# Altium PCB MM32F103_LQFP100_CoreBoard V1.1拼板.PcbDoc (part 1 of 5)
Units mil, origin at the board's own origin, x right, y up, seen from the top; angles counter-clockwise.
Board outline 7436.93 x 4329.96 mil, 2 copper layers (Top Layer, Bottom Layer); 260 components, 116 nets, 1796 pads, 452 vias.
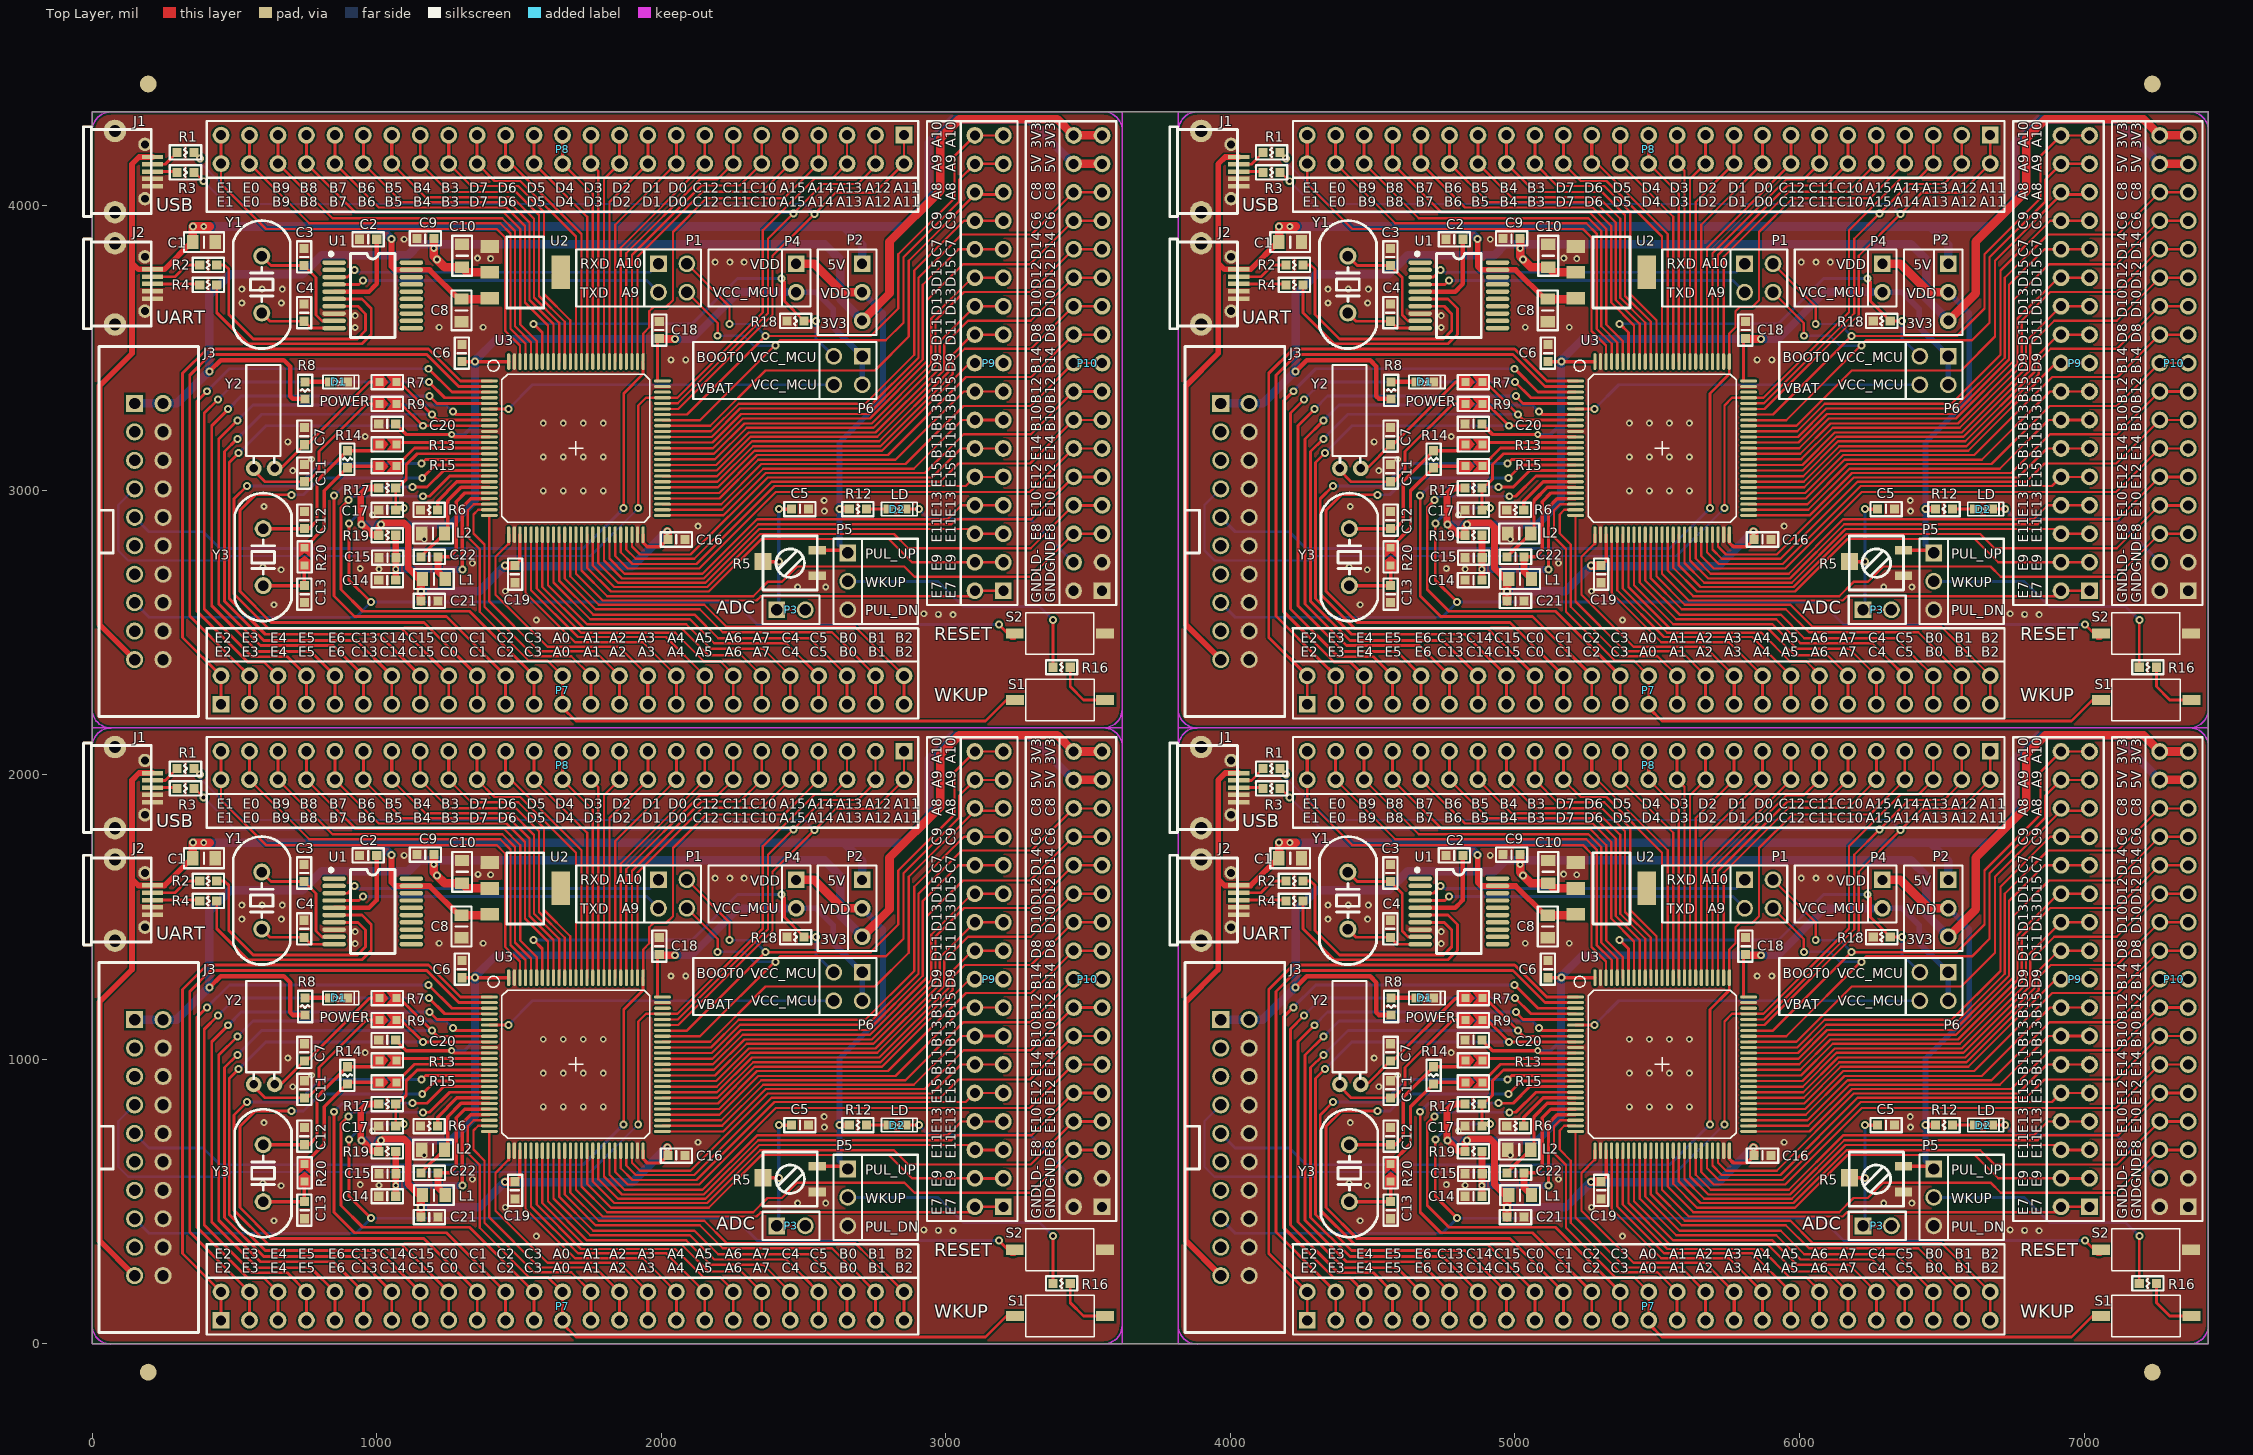
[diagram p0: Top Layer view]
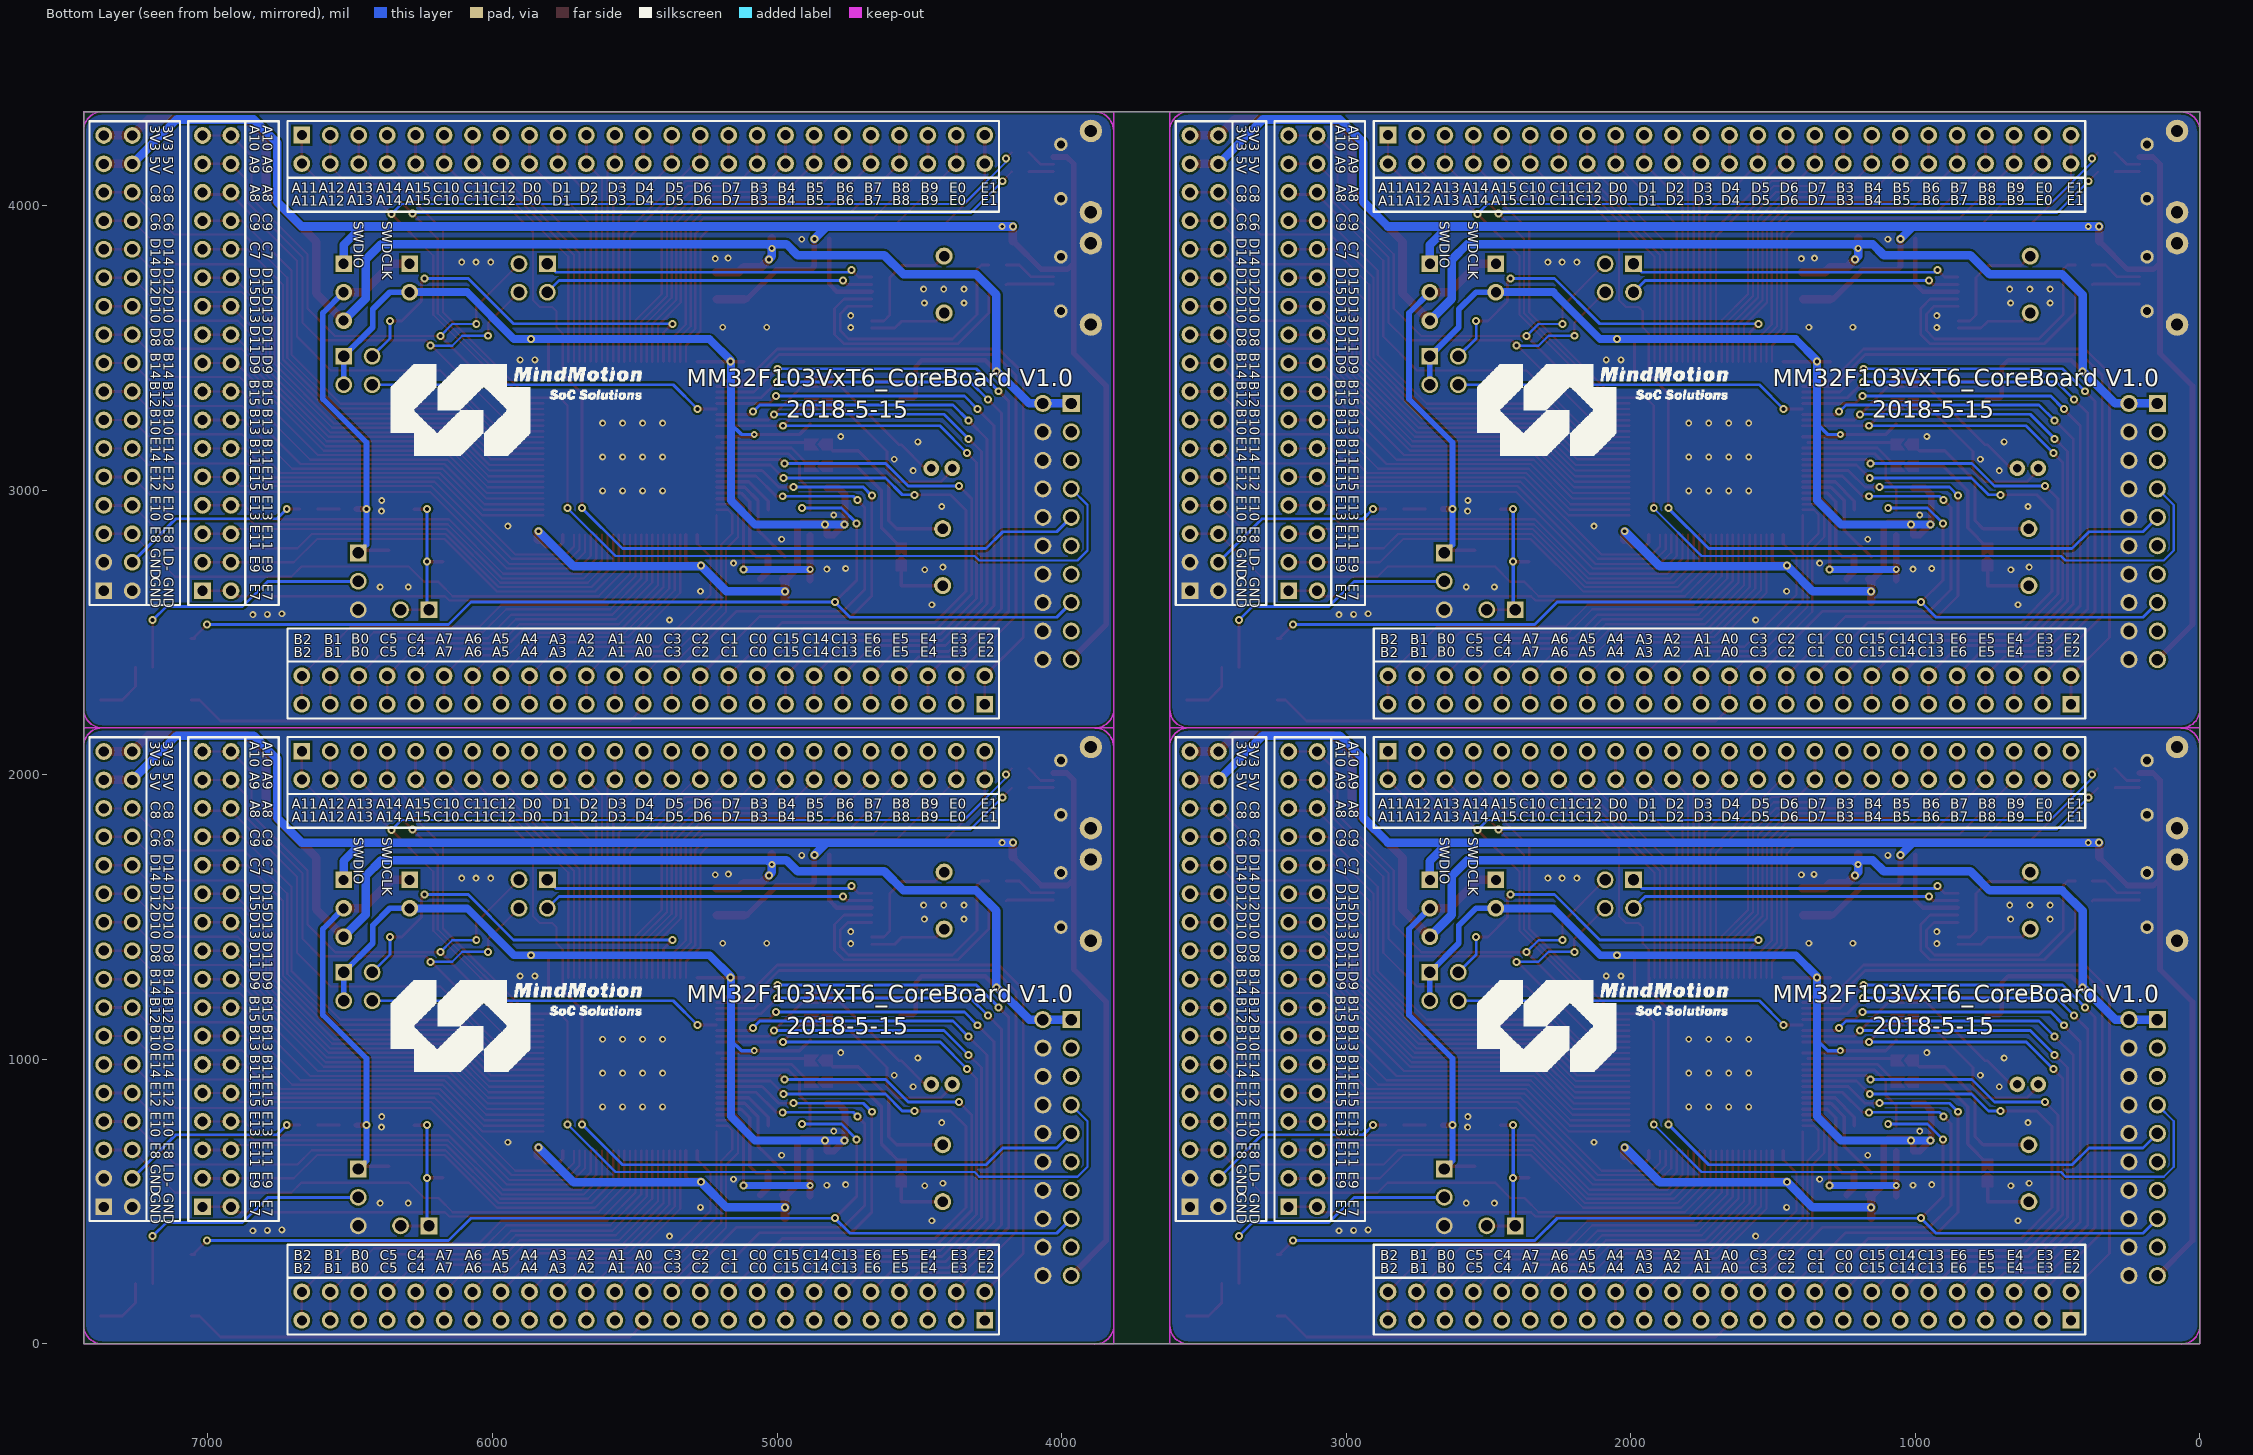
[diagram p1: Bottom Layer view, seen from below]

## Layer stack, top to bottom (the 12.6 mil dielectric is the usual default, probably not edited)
Top Layer: signal copper 1.4
Dielectric: dielectric 12.6, FR-4, Dk 4.8
Bottom Layer: signal copper 1.4

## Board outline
0,0 0,4329.96 7436.93,4329.96 7436.93,0

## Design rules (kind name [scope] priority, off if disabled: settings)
Clearance [All] p1: gap=7
MinimumSolderMaskSliver [All] p1: minsoldermaskwidth=7
PolygonConnect [All] p1: connectstyle=Direct reliefconductorwidth=10 reliefentries=4 polygonreliefangle="90 Angle"
RoutingVias [All] p1: holewidth=28 width=50 viastyle="Through Hole" minholewidth=14 minwidth=28 maxholewidth=30 maxwidth=50
SilkToSilkClearance [All] p1: silktosilkclearance=0
SilkscreenOverComponentPads [All] p1: minsilkscreentomaskgap=0
SolderMaskExpansion [All] p1: expansion=4
Width [All] p1: maxlimit=50 minlimit=8 preferedwidth=10
25 further rules are at their usual default settings.

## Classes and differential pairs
component class "MM32F103_LQFP100_CoreBoard V1.0": C1 C2 C3 C4 C5 C6 C7 C8 C9 C10 C11 C12 C13 C14 C15 C16 C17 C18 C19 C20 C21 C22 D1 D2 J1 J2 J3 L1 L2 P1 P2 P3 P4 P5 P6 P7 P8 P9 P10 P12 P14 R1 R2 R3 R4 R5 R6 R7 R8 R9 R12 R13 R14 R15 R16 R17 R18 R19 R20 S1 S2 U1 U2 U3 Y1 Y2 Y3

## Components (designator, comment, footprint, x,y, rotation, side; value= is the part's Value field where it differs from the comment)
C1 "4.7uF" C-0805 393,1707 r180 top
C1 "4.7uF" C-0805 4209.93,1707 r180 top
C1 "4.7uF" C-0805 393,3872 r180 top
C1 "4.7uF" C-0805 4209.93,3872 r180 top
C2 "104" C-0603 970,1717 r0 top
C2 "104" C-0603 4786.93,1717 r0 top
C2 "104" C-0603 970,3882 r0 top
C2 "104" C-0603 4786.93,3882 r0 top
C3 "22pF" C-0603 745,1655 r270 top
C3 "22pF" C-0603 4561.93,1655 r270 top
C3 "22pF" C-0603 745,3820 r270 top
C3 "22pF" C-0603 4561.93,3820 r270 top
C4 "22pF" C-0603 745,1459 r270 top
C4 "22pF" C-0603 4561.93,1459 r270 top
C4 "22pF" C-0603 745,3624 r270 top
C4 "22pF" C-0603 4561.93,3624 r270 top
C5 "104" C-0603 2487.23,769 r180 top
C5 "104" C-0603 6304.16,769 r180 top
C5 "104" C-0603 2487.23,2934 r180 top
C5 "104" C-0603 6304.16,2934 r180 top
C6 "104" C-0603 1299,1317 r90 top
C6 "104" C-0603 5115.93,1317 r90 top
C6 "104" C-0603 1299,3482 r90 top
C6 "104" C-0603 5115.93,3482 r90 top
C7 "15pF" C-0603 746,1025 r270 top
C7 "15pF" C-0603 4562.93,1025 r270 top
C7 "15pF" C-0603 746,3190 r270 top
C7 "15pF" C-0603 4562.93,3190 r270 top
C8 "4.7uF" C-0805 1298,1467 r90 top
C8 "4.7uF" C-0805 5114.93,1467 r90 top
C8 "4.7uF" C-0805 1298,3632 r90 top
C8 "4.7uF" C-0805 5114.93,3632 r90 top
C9 "104" C-0603 1171,1720 r0 top
C9 "104" C-0603 4987.93,1720 r0 top
C9 "104" C-0603 1171,3885 r0 top
C9 "104" C-0603 4987.93,3885 r0 top
C10 "10uF" C-0805 1300,1659 r270 top
C10 "10uF" C-0805 5116.93,1659 r270 top
C10 "10uF" C-0805 1300,3824 r270 top
C10 "10uF" C-0805 5116.93,3824 r270 top
C11 "15pF" C-0603 746,895 r270 top
C11 "15pF" C-0603 4562.93,895 r270 top
C11 "15pF" C-0603 746,3060 r270 top
C11 "15pF" C-0603 4562.93,3060 r270 top
C12 "22pF" C-0603 746,730 r270 top
C12 "22pF" C-0603 4562.93,730 r270 top
C12 "22pF" C-0603 746,2895 r270 top
C12 "22pF" C-0603 4562.93,2895 r270 top
C13 "22pF" C-0603 746,470 r90 top
C13 "22pF" C-0603 4562.93,470 r90 top
C13 "22pF" C-0603 746,2635 r90 top
C13 "22pF" C-0603 4562.93,2635 r90 top
C14 "1uF" C-0603 1037,519 r180 top
C14 "1uF" C-0603 4853.93,519 r180 top
C14 "1uF" C-0603 1037,2684 r180 top
C14 "1uF" C-0603 4853.93,2684 r180 top
C15 "103" C-0603 1038,598 r180 top
C15 "103" C-0603 4854.93,598 r180 top
C15 "103" C-0603 1038,2763 r180 top
C15 "103" C-0603 4854.93,2763 r180 top
C16 "104" C-0603 2053,662 r180 top
C16 "104" C-0603 5869.93,662 r180 top
C16 "104" C-0603 2053,2827 r180 top
C16 "104" C-0603 5869.93,2827 r180 top
C17 "104" C-0603 1037,765.86 r180 top
C17 "104" C-0603 4853.93,765.86 r180 top
C17 "104" C-0603 1037,2930.86 r180 top
C17 "104" C-0603 4853.93,2930.86 r180 top
C18 "104" C-0603 1993,1398 r90 top
C18 "104" C-0603 5809.93,1398 r90 top
C18 "104" C-0603 1993,3563 r90 top
C18 "104" C-0603 5809.93,3563 r90 top
C19 "104" C-0603 1486,540 r270 top
C19 "104" C-0603 5302.93,540 r270 top
C19 "104" C-0603 1486,2705 r270 top
C19 "104" C-0603 5302.93,2705 r270 top
C20 "104" C-0603 1037,1068 r180 top
C20 "104" C-0603 4853.93,1068 r180 top
C20 "104" C-0603 1037,3233 r180 top
C20 "104" C-0603 4853.93,3233 r180 top
C21 "1uF" C-0603 1185,446 r0 top
C21 "1uF" C-0603 5001.93,446 r0 top
C21 "1uF" C-0603 1185,2611 r0 top
C21 "1uF" C-0603 5001.93,2611 r0 top
C22 "1uF" C-0603 1185,601 r180 top
C22 "1uF" C-0603 5001.93,601 r180 top
C22 "1uF" C-0603 1185,2766 r180 top
C22 "1uF" C-0603 5001.93,2766 r180 top
D1 "RED" LED-0603 866,1216 r270 top
D1 "RED" LED-0603 4682.93,1216 r270 top
D1 "RED" LED-0603 866,3381 r270 top
D1 "RED" LED-0603 4682.93,3381 r270 top
D2 "BLUE" LED-0603 2829,769 r270 top
D2 "BLUE" LED-0603 6645.93,769 r270 top
D2 "BLUE" LED-0603 2829,2934 r270 top
D2 "BLUE" LED-0603 6645.93,2934 r270 top
J1 "USB_Micro_OX" USB_MICRO_OX_S 206,1955 r90 top
J1 "USB_Micro_OX" USB_MICRO_OX_S 4022.93,1955 r90 top
J1 "USB_Micro_OX" USB_MICRO_OX_S 206,4120 r90 top
J1 "USB_Micro_OX" USB_MICRO_OX_S 4022.93,4120 r90 top
J2 "USB_Micro_OX" USB_MICRO_OX_S 206,1560 r90 top
J2 "USB_Micro_OX" USB_MICRO_OX_S 4022.93,1560 r90 top
J2 "USB_Micro_OX" USB_MICRO_OX_S 206,3725 r90 top
J2 "USB_Micro_OX" USB_MICRO_OX_S 4022.93,3725 r90 top
J3 "CON20A" HEADERBG10X2H 149,1140 r90 top
J3 "CON20A" HEADERBG10X2H 3965.93,1140 r90 top
J3 "CON20A" HEADERBG10X2H 149,3305 r90 top
J3 "CON20A" HEADERBG10X2H 3965.93,3305 r90 top
L1 "Res Semi" C-0805 1201,523 r0 top
L1 "Res Semi" C-0805 5017.93,523 r0 top
L1 "Res Semi" C-0805 1201,2688 r0 top
L1 "Res Semi" C-0805 5017.93,2688 r0 top
L2 "Res Semi" C-0805 1198,682.86 r0 top
L2 "Res Semi" C-0805 5014.93,682.86 r0 top
L2 "Res Semi" C-0805 1198,2847.86 r0 top
L2 "Res Semi" C-0805 5014.93,2847.86 r0 top
P1 "Header 2X2" HDR2X2 1990,1631 r270 top
P1 "Header 2X2" HDR2X2 5806.93,1631 r270 top
P1 "Header 2X2" HDR2X2 1990,3796 r270 top
P1 "Header 2X2" HDR2X2 5806.93,3796 r270 top
P2 "Header 3" HDR1X3#1 2706,1631 r270 top
P2 "Header 3" HDR1X3#1 6522.93,1631 r270 top
P2 "Header 3" HDR1X3#1 2706,3796 r270 top
P2 "Header 3" HDR1X3#1 6522.93,3796 r270 top
P3 "Header 2" HDR1X2#1 2406,415 r0 top
P3 "Header 2" HDR1X2#1 6222.93,415 r0 top
P3 "Header 2" HDR1X2#1 2406,2580 r0 top
P3 "Header 2" HDR1X2#1 6222.93,2580 r0 top
P4 "Header 2" HDR1X2#2 2474,1631 r270 top
P4 "Header 2" HDR1X2#2 6290.93,1631 r270 top
P4 "Header 2" HDR1X2#2 2474,3796 r270 top
P4 "Header 2" HDR1X2#2 6290.93,3796 r270 top
P5 "Header 3" HDR1X3#2 2655,615 r270 top
P5 "Header 3" HDR1X3#2 6471.93,615 r270 top
P5 "Header 3" HDR1X3#2 2655,2780 r270 top
P5 "Header 3" HDR1X3#2 6471.93,2780 r270 top
P6 "Header 2X2" HDR2X2 2706,1305.94 r180 top
P6 "Header 2X2" HDR2X2 6522.93,1305.94 r180 top
P6 "Header 2X2" HDR2X2 2706,3470.94 r180 top
P6 "Header 2X2" HDR2X2 6522.93,3470.94 r180 top
P7 "Header 25X2" HDR2X25 453,83 r0 top
P7 "Header 25X2" HDR2X25 4269.93,83 r0 top
P7 "Header 25X2" HDR2X25 453,2248 r0 top
P7 "Header 25X2" HDR2X25 4269.93,2248 r0 top
P8 "Header 25X2" HDR2X25 2853,2083 r180 top
P8 "Header 25X2" HDR2X25 6669.93,2083 r180 top
P8 "Header 25X2" HDR2X25 2853,4248 r180 top
P8 "Header 25X2" HDR2X25 6669.93,4248 r180 top
P9 "Header 17X2" HDR2X17 3202,482 r90 top
P9 "Header 17X2" HDR2X17 7018.93,482 r90 top
P9 "Header 17X2" HDR2X17 3202,2647 r90 top
P9 "Header 17X2" HDR2X17 7018.93,2647 r90 top
P10 "Header 17X2" HDR2X17 3549,482 r90 top
P10 "Header 17X2" HDR2X17 7365.93,482 r90 top
P10 "Header 17X2" HDR2X17 3549,2647 r90 top
P10 "Header 17X2" HDR2X17 7365.93,2647 r90 top
R1 "22R" R-0603 328,2022 r0 top
R1 "22R" R-0603 4144.93,2022 r0 top
R1 "22R" R-0603 328,4187 r0 top
R1 "22R" R-0603 4144.93,4187 r0 top
R2 "22R" R-0603 408,1627 r0 top
R2 "22R" R-0603 4224.93,1627 r0 top
R2 "22R" R-0603 408,3792 r0 top
R2 "22R" R-0603 4224.93,3792 r0 top
R3 "22R" R-0603 328,1952 r0 top
R3 "22R" R-0603 4144.93,1952 r0 top
R3 "22R" R-0603 328,4117 r0 top
R3 "22R" R-0603 4144.93,4117 r0 top
R4 "22R" R-0603 408,1557 r0 top
R4 "22R" R-0603 4224.93,1557 r0 top
R4 "22R" R-0603 408,3722 r0 top
R4 "22R" R-0603 4224.93,3722 r0 top
R5 "10K" R-VR-S 2453,579 r90 top
R5 "10K" R-VR-S 6269.93,579 r90 top
R5 "10K" R-VR-S 2453,2744 r90 top
R5 "10K" R-VR-S 6269.93,2744 r90 top
R6 "0R" R-0603 1184,765.71 r180 top
R6 "0R" R-0603 5000.93,765.71 r180 top
R6 "0R" R-0603 1184,2930.71 r180 top
R6 "0R" R-0603 5000.93,2930.71 r180 top
R7 "NC" NC-0603#1 1009,1216.14 r0 top
R7 "NC" NC-0603#1 4825.93,1216.14 r0 top
R7 "NC" NC-0603#1 1009,3381.14 r0 top
R7 "NC" NC-0603#1 4825.93,3381.14 r0 top
R8 "4.7K" R-0603 748,1186 r270 top
R8 "4.7K" R-0603 4564.93,1186 r270 top
R8 "4.7K" R-0603 748,3351 r270 top
R8 "4.7K" R-0603 4564.93,3351 r270 top
R9 "NC" NC-0603#1 1009,1139.29 r0 top
R9 "NC" NC-0603#1 4825.93,1139.29 r0 top
R9 "NC" NC-0603#1 1009,3304.29 r0 top
R9 "NC" NC-0603#1 4825.93,3304.29 r0 top
R12 "3K" R-0603 2690.7,769 r180 top
R12 "3K" R-0603 6507.63,769 r180 top
R12 "3K" R-0603 2690.7,2934 r180 top
R12 "3K" R-0603 6507.63,2934 r180 top
R13 "NC" NC-0603#1 1009,997.43 r0 top
R13 "NC" NC-0603#1 4825.93,997.43 r0 top
R13 "NC" NC-0603#1 1009,3162.43 r0 top
R13 "NC" NC-0603#1 4825.93,3162.43 r0 top
R14 "510K" R-0603 897,944 r270 top
R14 "510K" R-0603 4713.93,944 r270 top
R14 "510K" R-0603 897,3109 r270 top
R14 "510K" R-0603 4713.93,3109 r270 top
R15 "NC" NC-0603#1 1009,920.57 r0 top
R15 "NC" NC-0603#1 4825.93,920.57 r0 top
R15 "NC" NC-0603#1 1009,3085.57 r0 top
R15 "NC" NC-0603#1 4825.93,3085.57 r0 top
R16 "1K" R-0603 3407,213 r0 top
R16 "1K" R-0603 7223.93,213 r0 top
R16 "1K" R-0603 3407,2378 r0 top
R16 "1K" R-0603 7223.93,2378 r0 top
R17 "47K" R-0603 1037,842.71 r180 top
R17 "47K" R-0603 4853.93,842.71 r180 top
R17 "47K" R-0603 1037,3007.71 r180 top
R17 "47K" R-0603 4853.93,3007.71 r180 top
R18 "4.7K" R-0603 2472,1430 r0 top
R18 "4.7K" R-0603 6288.93,1430 r0 top
R18 "4.7K" R-0603 2472,3595 r0 top
R18 "4.7K" R-0603 6288.93,3595 r0 top
R19 "0R" R-0603 1037,677 r180 top
R19 "0R" R-0603 4853.93,677 r180 top
R19 "0R" R-0603 1037,2842 r180 top
R19 "0R" R-0603 4853.93,2842 r180 top
R20 "510R" NC-0603#2 746,575 r90 top
R20 "510R" NC-0603#2 4562.93,575 r90 top
R20 "510R" NC-0603#2 746,2740 r90 top
R20 "510R" NC-0603#2 4562.93,2740 r90 top
S1 "SW-PB" 3x6x2.5 3281,171 r0 top
S1 "SW-PB" 3x6x2.5 7097.93,171 r0 top
S1 "SW-PB" 3x6x2.5 3281,2336 r0 top
S1 "SW-PB" 3x6x2.5 7097.93,2336 r0 top
S2 "SW-PB" 3x6x2.5 3280,404 r0 top
S2 "SW-PB" 3x6x2.5 7096.93,404 r0 top
S2 "SW-PB" 3x6x2.5 3280,2569 r0 top
S2 "SW-PB" 3x6x2.5 7096.93,2569 r0 top
U1 "CH340T" SSOP-20_208MIL 986,1520 r270 top
U1 "CH340T" SSOP-20_208MIL 4802.93,1520 r270 top
U1 "CH340T" SSOP-20_208MIL 986,3685 r270 top
U1 "CH340T" SSOP-20_208MIL 4802.93,3685 r270 top
U2 "LD1117" SOT223 1522,1601 r270 top
U2 "LD1117" SOT223 5338.93,1601 r270 top
U2 "LD1117" SOT223 1522,3766 r270 top
U2 "LD1117" SOT223 5338.93,3766 r270 top
U3 "MM32F103VET6" LQFP100 1700,983 r0 top
U3 "MM32F103VET6" LQFP100 5516.93,983 r0 top
U3 "MM32F103VET6" LQFP100 1700,3148 r0 top
U3 "MM32F103VET6" LQFP100 5516.93,3148 r0 top
Y1 "12M" X'TAL 596,1458 r90 top
Y1 "12M" X'TAL 4412.93,1458 r90 top
Y1 "12M" X'TAL 596,3623 r90 top
Y1 "12M" X'TAL 4412.93,3623 r90 top
Y2 "32.768K" X'TAL-32768 641,912 r180 top
Y2 "32.768K" X'TAL-32768 4457.93,912 r180 top
Y2 "32.768K" X'TAL-32768 641,3077 r180 top
Y2 "32.768K" X'TAL-32768 4457.93,3077 r180 top
Y3 "8M" X'TAL 601,500 r90 top
Y3 "8M" X'TAL 4417.93,500 r90 top
Y3 "8M" X'TAL 601,2665 r90 top
Y3 "8M" X'TAL 4417.93,2665 r90 top

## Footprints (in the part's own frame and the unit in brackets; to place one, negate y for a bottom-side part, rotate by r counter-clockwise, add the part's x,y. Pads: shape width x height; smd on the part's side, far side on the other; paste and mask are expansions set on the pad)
3x6x2.5 [mm]
  rect 1.6x0.9 smd: 1(-0.965,-1.85) 2(7.087,-1.85)
  silkscreen extent 0,-3.71 6.1,0
C-0603 [mil]
  rect 32x32 smd: 1(-30,0) 2(30,0)
  silkscreen extent -55,-25 55,25
C-0805 [mil]
  rect 40x50 smd: 1(-40,0) 2(40,0)
  silkscreen extent -70,-35 70,35
HDR1X2#1 [mm] "Connector; Header; 2 Position"
  rect 1.5x1.5 hole 1.016: 1(0,0)
  round 1.5 hole 1.016: 2(2.54,0)
  silkscreen extent -1.27,-1.27 3.81,1.27
HDR1X2#2 [mm] "Connector; Header; 2 Position"
  rect 1.5x1.5 hole 0.9: 1(0,0)
  round 1.5 hole 0.9: 2(2.54,0)
  silkscreen extent -1.27,-1.27 3.81,1.27
HDR1X3#1 [mm] "Connector; Header; 3 Position"
  rect 1.5x1.5 hole 0.9: 1(0,0)
  round 1.5 hole 0.9: 2(2.54,0) 3(5.08,0)
  silkscreen extent -1.27,-1.27 6.35,1.27
HDR1X3#2 [mm] "Connector; Header; 3 Position"
  rect 1.5x1.5 hole 1.016: 1(0,0)
  round 1.5 hole 1.016: 2(2.54,0) 3(5.08,0)
  silkscreen extent -1.27,-1.27 6.35,1.27
HDR2X2 [mm] "Connector; Header; 2x2 Position"
  rect 1.5x1.5 hole 1.016: 1(0,0)
  round 1.5 hole 1.016: 2(0,2.54) 3(2.54,0) 4(2.54,2.54)
  silkscreen extent -1.27,-1.27 3.81,3.81
HDR2X17 [mm] "Connector; Header; 17x2 Position"
  rect 1.5x1.5 hole 0.9: 1(0,0)
  round 1.5 hole 0.9: 2(0,2.54) 3(2.54,0) 4(2.54,2.54) 5(5.08,0) 6(5.08,2.54) 7(7.62,0) 8(7.62,2.54) 9(10.16,0) 10(10.16,2.54) 11(12.7,0) 12(12.7,2.54) 13(15.24,0) 14(15.24,2.54) 15(17.78,0) 16(17.78,2.54) 17(20.32,0) 18(20.32,2.54) 19(22.86,0) 20(22.86,2.54) 21(25.4,0) 22(25.4,2.54) 23(27.94,0) 24(27.94,2.54) 25(30.48,0) 26(30.48,2.54) 27(33.02,0) 28(33.02,2.54) 29(35.56,0) 30(35.56,2.54) 31(38.1,0) 32(38.1,2.54) 33(40.64,0) 34(40.64,2.54)
  silkscreen extent -1.27,-1.27 41.91,3.81
HDR2X25 [mm] "Connector; Header; 25x2 Position"
  rect 1.5x1.5 hole 0.9: 1(0,0)
  round 1.5 hole 0.9: 2(0,2.54) 3(2.54,0) 4(2.54,2.54) 5(5.08,0) 6(5.08,2.54) 7(7.62,0) 8(7.62,2.54) 9(10.16,0) 10(10.16,2.54) 11(12.7,0) 12(12.7,2.54) 13(15.24,0) 14(15.24,2.54) 15(17.78,0) 16(17.78,2.54) 17(20.32,0) 18(20.32,2.54) 19(22.86,0) 20(22.86,2.54) 21(25.4,0) 22(25.4,2.54) 23(27.94,0) 24(27.94,2.54) 25(30.48,0) 26(30.48,2.54) 27(33.02,0) 28(33.02,2.54) 29(35.56,0) 30(35.56,2.54) 31(38.1,0) 32(38.1,2.54) 33(40.64,0) 34(40.64,2.54) 35(43.18,0) 36(43.18,2.54) 37(45.72,0) 38(45.72,2.54) 39(48.26,0) 40(48.26,2.54) 41(50.8,0) 42(50.8,2.54) 43(53.34,0) 44(53.34,2.54) 45(55.88,0) 46(55.88,2.54) 47(58.42,0) 48(58.42,2.54) 49(60.96,0) 50(60.96,2.54)
  silkscreen extent -1.27,-1.27 62.23,3.81
HEADERBG10X2H [mil]
  rect 60x60 hole 40: 1(0,0)
  round 60 hole 40: 2(0,-100) 3(-100,0) 4(-100,-100) 5(-200,0) 6(-200,-100) 7(-300,0) 8(-300,-100) 9(-400,0) 10(-400,-100) 11(-500,0) 12(-500,-100) 13(-600,0) 14(-600,-100) 15(-700,0) 16(-700,-100) 17(-800,0) 18(-800,-100) 19(-900,0) 20(-900,-100)
  silkscreen extent -1100,-225 200,125
LED-0603 [mm]
  rect 0.8x0.8 smd: 1(0,-0.8) 2(0,0.8)
  silkscreen extent -0.6,-1.4 0.6,1.8
LQFP100 [mm]
  oval 1.5x0.279 smd: 1(-7.725,6) 2(-7.725,5.5) 3(-7.725,5) 4(-7.725,4.5) 5(-7.725,4) 6(-7.725,3.5) 7(-7.725,3) 8(-7.725,2.5) 9(-7.725,2) 10(-7.725,1.5) 11(-7.725,1) 12(-7.725,0.5) 13(-7.725,0) 14(-7.725,-0.5) 15(-7.725,-1) 16(-7.725,-1.5) 17(-7.725,-2) 18(-7.725,-2.5) 19(-7.725,-3) 20(-7.725,-3.5) 21(-7.725,-4) 22(-7.725,-4.5) 23(-7.725,-5) 24(-7.725,-5.5) 25(-7.725,-6) 51(7.725,-6) 52(7.725,-5.5) 53(7.725,-5) 54(7.725,-4.5) 55(7.725,-4) 56(7.725,-3.5) 57(7.725,-3) 58(7.725,-2.5) 59(7.725,-2) 60(7.725,-1.5) 61(7.725,-1) 62(7.725,-0.5) 63(7.725,0) 64(7.725,0.5) 65(7.725,1) 66(7.725,1.5) 67(7.725,2) 68(7.725,2.5) 69(7.725,3) 70(7.725,3.5) 71(7.725,4) 72(7.725,4.5) 73(7.725,5) 74(7.725,5.5) 75(7.725,6)
  oval 0.279x1.5 smd: 26(-6,-7.725) 27(-5.5,-7.725) 28(-5,-7.725) 29(-4.5,-7.725) 30(-4,-7.725) 31(-3.5,-7.725) 32(-3,-7.725) 33(-2.5,-7.725) 34(-2,-7.725) 35(-1.5,-7.725) 36(-1,-7.725) 37(-0.5,-7.725) 38(0,-7.725) 39(0.5,-7.725) 40(1,-7.725) 41(1.5,-7.725) 42(2,-7.725) 43(2.5,-7.725) 44(3,-7.725) 45(3.5,-7.725) 46(4,-7.725) 47(4.5,-7.725) 48(5,-7.725) 49(5.5,-7.725) 50(6,-7.725) 76(6,7.725) 77(5.5,7.725) 78(5,7.725) 79(4.5,7.725) 80(4,7.725) 81(3.5,7.725) 82(3,7.725) 83(2.5,7.725) 84(2,7.725) 85(1.5,7.725) 86(1,7.725) 87(0.5,7.725) 88(0,7.725) 89(-0.5,7.725) 90(-1,7.725) 91(-1.5,7.725) 92(-2,7.725) 93(-2.5,7.725) 94(-3,7.725) 95(-3.5,7.725) 96(-4,7.725) 97(-4.5,7.725) 98(-5,7.725) 99(-5.5,7.725) 100(-6,7.725)
  silkscreen extent -7.86,-6.6 6.6,7.87
NC-0603#1 [mil]
  rect 28x28 smd: 1(0,-1) 2(60,-1)
  Top Layer region: -22,-21 16,-21 32,-1 16,19 -22,19
  Top Layer region: 26,19 42,-1 26,-21 78,-21 78,19
  silkscreen extent -27,-26 83,24
NC-0603#2 [mil]
  rect 28x28 smd: 1(-4,-0.33) 2(58,-0.33)
  Top Layer region: -24,-20.33 14,-20.33 30,-0.33 14,19.67 -24,19.67
  Top Layer region: 24,19.67 40,-0.33 24,-20.33 76,-20.33 76,19.67
  silkscreen extent -29,-25 81,25
R-0603 [mil]
  rect 32x32 smd: 1(-30,0) 2(30,0)
  silkscreen extent -55,-25 55,25
R-VR-S [mil]
  rect 30x60 smd: 1(-45,-95) 3(45,-95)
  rect 60x60 smd: 2(5,95)
  silkscreen extent -95,-95 95,95
SOT223 [mil]
  rect 45x65 smd: 1(-91,-125) 2(0,-125) 3(91,-125)
  rect 118x65 smd: 4(0,125)
  silkscreen extent -125,-65 125,65
SSOP-20_208MIL [mm]
  oval 0.4x2.1 smd mask+0.051: 1(-2.925,-3.45) 2(-2.275,-3.45) 3(-1.625,-3.45) 4(-0.975,-3.45) 5(-0.325,-3.45) 6(0.325,-3.45) 7(0.975,-3.45) 8(1.625,-3.45) 9(2.275,-3.45) 10(2.925,-3.45) 11(2.925,3.45) 12(2.275,3.45) 13(1.625,3.45) 14(0.975,3.45) 15(0.325,3.45) 16(-0.325,3.45) 17(-0.975,3.45) 18(-1.625,3.45) 19(-2.275,3.45) 20(-2.925,3.45)
  silkscreen extent -3.85,-3.86 3.75,2
USB_MICRO_OX_S [mm]
  rect 0.4x1.905 smd: 1(1.3,-0.153) 2(0.65,-0.153) 3(0,-0.153) 4(-0.65,-0.153) 5(-1.3,-0.153)
  round 1.2 hole 0.7: 6(2.425,0.52) 7(-2.425,0.52)
  round 2 hole 1.1: 8(-3.625,3.2) 9(3.625,3.2)
  silkscreen extent -4,-0.04 4,6
X'TAL [mil]
  round 60 hole 37: 1(0,0) 2(200,0)
  silkscreen extent -125,-100 325,100
X'TAL-32768 [mil]
  round 55 hole 30: 1(73.35,0) 2(0,0)
  silkscreen extent -21,-363 99,-20

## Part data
C1 C1 C1 C1 C2 C2 C2 C2 C3 C3 C3 C3 C4 C4 C4 C4 C5 C5 C5 C5 C6 C6 C6 C6 C7 C7 C7 C7 C8 C8 C8 C8 C9 C9 C9 C9 C10 C10 C10 C10 C11 C11 C11 C11 C12 C12 C12 C12 C13 C13 C13 C13 C14 C14 C14 C14 C15 C15 C15 C15 C16 C16 C16 C16 C18 C18 C18 C18 C19 C19 C19 C19 C20 C20 C20 C20 C21 C21 C21 C21 C22 C22 C22 C22: library part CAP, "Capacitor"
C17 C17 C17 C17: library part Cap, "Capacitor"
D1 D1 D1 D1 D2 D2 D2 D2: library part LED0, "Typical INFRARED GaAs LED"
L1 L1 L1 L1 L2 L2 L2 L2: "Semiconductor Resistor"
P1 P1 P1 P1 P6 P6 P6 P6: "Header, 2-Pin, Dual row"
P2 P2 P2 P2 P5 P5 P5 P5: "Header, 3-Pin"
P3 P3 P3 P3 P4 P4 P4 P4: "Header, 2-Pin"
P7 P7 P7 P7 P8 P8 P8 P8: "Header, 25-Pin, Dual row"
P9 P9 P9 P9 P10 P10 P10 P10: "Header, 17-Pin, Dual row"
R1 R1 R1 R1 R2 R2 R2 R2 R3 R3 R3 R3 R4 R4 R4 R4 R6 R6 R6 R6 R7 R7 R7 R7 R8 R8 R8 R8 R9 R9 R9 R9 R12 R12 R12 R12 R13 R13 R13 R13 R15 R15 R15 R15 R16 R16 R16 R16 R17 R17 R17 R17 R18 R18 R18 R18 R19 R19 R19 R19 R20 R20 R20 R20: library part Res2, "Resistor"
R5 R5 R5 R5: library part "RESISTOR VAR"
R14 R14 R14 R14: library part RES
S1 S1 S1 S1 S2 S2 S2 S2: "Switch"
U2 U2 U2 U2: library part LD1117/SOT_0
U3 U3 U3 U3: library part LQFP100
Y1 Y1 Y1 Y1 Y2 Y2 Y2 Y2 Y3 Y3 Y3 Y3: library part XTAL, "Crystal Oscillator"

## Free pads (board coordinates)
  round 59.06 smd: 1(197,-99) 1(197,4427.81) 1(7239.93,-99) 1(7239.93,4427.81)
  round 157.48 on Top Solder: 2(197,-99) 2(197,4427.81) 2(7239.93,-99) 2(7239.93,4427.81)

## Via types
v1: diameter 28, hole 14, Top Layer to Bottom Layer, 228 vias
v2: diameter 24, hole 12, Top Layer to Bottom Layer, 224 vias

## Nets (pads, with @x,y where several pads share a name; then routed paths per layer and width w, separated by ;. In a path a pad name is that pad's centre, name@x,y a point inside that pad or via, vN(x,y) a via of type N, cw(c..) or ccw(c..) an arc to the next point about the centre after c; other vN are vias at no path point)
3V3: C9.2 C10.2 J3.1 J3.2 P2.3 P10.33 P10.34 R8.2 U2.2 | length 21321.7
  Top Layer w16: v1(412.19,1252.81) 451.37,1292 674,1292 696,1270 696,1165 705,1156 R8.2@748,1156 ; v1(412.19,3417.81) 451.37,3457 674,3457 696,3435 696,3330 705,3321 R8.2@748,3321 ; v1(4229.12,1252.81) 4268.3,1292 4490.93,1292 4512.93,1270 4512.93,1165 4521.93,1156 R8.2@4564.93,1156 ; v1(4229.12,3417.81) 4268.3,3457 4490.93,3457 4512.93,3435 4512.93,3330 4521.93,3321 R8.2@4564.93,3321
  Top Layer w30: v2@1201,1683 1201,1657 v1(1211.24,1646.76) 1239,1619 C10.2@1300,1619 1318,1601 U2.2@1397,1601 ; v2(1201,1685) C9.2@1201,1720 ; v2@1201,3848 1201,3822 v1(1211.24,3811.76) 1239,3784 C10.2@1300,3784 1318,3766 U2.2@1397,3766 ; v2(1201,3850) C9.2@1201,3885 ; P2.3@2706,1431 2802,1527 2802,1709 2980,1887 2980,2072 3047,2139 3392,2139 P10.34@3449,2082 P10.33@3549,2082 ; P2.3@2706,3596 2802,3692 2802,3874 2980,4052 2980,4237 3047,4304 3392,4304 P10.34@3449,4247 P10.33@3549,4247 ; v2@5017.93,1683 5017.93,1657 v1(5028.16,1646.76) 5055.93,1619 C10.2@5116.93,1619 5134.93,1601 U2.2@5213.93,1601 ; v2(5017.93,1685) C9.2@5017.93,1720 ; v2@5017.93,3848 5017.93,3822 v1(5028.16,3811.76) 5055.93,3784 C10.2@5116.93,3784 5134.93,3766 U2.2@5213.93,3766 ; v2(5017.93,3850) C9.2@5017.93,3885 ; P2.3@6522.93,1431 6618.93,1527 6618.93,1709 6796.93,1887 6796.93,2072 6863.93,2139 7208.93,2139 P10.34@7265.93,2082 P10.33@7365.93,2082 ; P2.3@6522.93,3596 6618.93,3692 6618.93,3874 6796.93,4052 6796.93,4237 6863.93,4304 7208.93,4304 P10.34@7265.93,4247 P10.33@7365.93,4247
  Bottom Layer w30: J3.1@149,1140 J3.2@249,1140 297,1140 v1@409.81,1252.81 ; J3.1@149,3305 J3.2@249,3305 297,3305 v1@409.81,3417.81 ; v1(1211.24,1646.76) 1201,1657 v2(1201,1685) 1216,1700 ; v1(1211.24,3811.76) 1201,3822 v2(1201,3850) 1216,3865 ; P2.3@2706,1431 2629,1508 2629,1645 2574,1700 1216,1700 ; P2.3@2706,3596 2629,3673 2629,3810 2574,3865 1216,3865 ; J3.1@3965.93,1140 J3.2@4065.93,1140 4113.93,1140 v1@4226.74,1252.81 ; J3.1@3965.93,3305 J3.2@4065.93,3305 4113.93,3305 v1@4226.74,3417.81 ; v1(5028.16,1646.76) 5017.93,1657 v2(5017.93,1685) 5032.93,1700 ; v1(5028.16,3811.76) 5017.93,3822 v2(5017.93,3850) 5032.93,3865 ; P2.3@6522.93,1431 6445.93,1508 6445.93,1645 6390.93,1700 5032.93,1700 ; P2.3@6522.93,3596 6445.93,3673 6445.93,3810 6390.93,3865 5032.93,3865 ; v1@409.81,1252.81 v1(412.19,1252.81) v1@412.19,1255.19 ; v1@409.81,1252.81 v1@412.19,1255.19 ; v1@409.81,3417.81 v1(412.19,3417.81) v1@412.19,3420.19 ; v1@409.81,3417.81 v1@412.19,3420.19 ; v1@412.19,1255.19 412.19,1522.19 484,1594 739,1594 806,1661 1111,1661 1150,1700 1216,1700 ; v1@412.19,3420.19 412.19,3687.19 484,3759 739,3759 806,3826 1111,3826 1150,3865 1216,3865 ; v1@4226.74,1252.81 v1(4229.12,1252.81) v1@4229.12,1255.19 ; v1@4226.74,1252.81 v1@4229.12,1255.19 ; v1@4226.74,3417.81 v1(4229.12,3417.81) v1@4229.12,3420.19 ; v1@4226.74,3417.81 v1@4229.12,3420.19 ; v1@4229.12,1255.19 4229.12,1522.19 4300.93,1594 4555.93,1594 4622.93,1661 4927.93,1661 4966.93,1700 5032.93,1700 ; v1@4229.12,3420.19 4229.12,3687.19 4300.93,3759 4555.93,3759 4622.93,3826 4927.93,3826 4966.93,3865 5032.93,3865
+5V: C1.2 C8.2 J1.1 J2.1 J3.19 P2.1 P10.31 P10.32 U1.19 U2.3 | length 26204.6
  Top Layer w20: J3.19@149,240 26,363 26,1202 140,1316 140,1634 ; J3.19@149,2405 26,2528 26,3367 140,3481 140,3799 ; J1.1@212,2006.18 165,2006.18 140,1981.18 140,1646 140,1634 ; J1.1@212,4171.18 165,4171.18 140,4146.18 140,3811 140,3799 ; C1.2@353,1710 254.18,1611.18 J2.1@212,1611.18 162.82,1611.18 140,1634 ; C1.2@353,3875 254.18,3776.18 J2.1@212,3776.18 162.82,3776.18 140,3799 ; v1(1052,1718) 1052,1622 1064.43,1609.57 U1.19@1121.83,1609.57 1185.43,1609.57 1288,1507 C8.2@1298,1507 ; v1(1052,3883) 1052,3787 1064.43,3774.57 U1.19@1121.83,3774.57 1185.43,3774.57 1288,3672 C8.2@1298,3672 ; U2.3@1394,1507 U2.3@1397,1510 ; U2.3@1394,3672 U2.3@1397,3675 ; J3.19@3965.93,240 3842.93,363 3842.93,1202 3956.93,1316 3956.93,1634 ; J3.19@3965.93,2405 3842.93,2528 3842.93,3367 3956.93,3481 3956.93,3799 ; J1.1@4028.93,2006.18 3981.93,2006.18 3956.93,1981.18 3956.93,1646 3956.93,1634 ; J1.1@4028.93,4171.18 3981.93,4171.18 3956.93,4146.18 3956.93,3811 3956.93,3799 ; C1.2@4169.93,1710 4071.11,1611.18 J2.1@4028.93,1611.18 3979.75,1611.18 3956.93,1634 ; C1.2@4169.93,3875 4071.11,3776.18 J2.1@4028.93,3776.18 3979.75,3776.18 3956.93,3799 ; v1(4868.93,1718) 4868.93,1622 4881.36,1609.57 U1.19@4938.76,1609.57 5002.36,1609.57 5104.93,1507 C8.2@5114.93,1507 ; v1(4868.93,3883) 4868.93,3787 4881.36,3774.57 U1.19@4938.76,3774.57 5002.36,3774.57 5104.93,3672 C8.2@5114.93,3672 ; U2.3@5210.93,1507 U2.3@5213.93,1510 ; U2.3@5210.93,3672 U2.3@5213.93,3675
  Top Layer w30: C1.2@353,1710 354,1711 v1(354,1762) v2(392,1762) 413,1762 ; C1.2@353,3875 354,3876 v1(354,3927) v2(392,3927) 413,3927 ; C8.2@1298,1507 U2.3@1394,1507 ; C8.2@1298,3672 U2.3@1394,3672 ; P10.32@3449,1982 P10.31@3549,1982 ; P10.32@3449,4147 P10.31@3549,4147 ; C1.2@4169.93,1710 4170.93,1711 v1(4170.93,1762) v2(4208.93,1762) 4229.93,1762 ; C1.2@4169.93,3875 4170.93,3876 v1(4170.93,3927) v2(4208.93,3927) 4229.93,3927 ; C8.2@5114.93,1507 U2.3@5210.93,1507 ; C8.2@5114.93,3672 U2.3@5210.93,3672 ; P10.32@7265.93,1982 P10.31@7365.93,1982 ; P10.32@7265.93,4147 P10.31@7365.93,4147
  Bottom Layer w30: v1(354,1762) v2(392,1762) 983,1762 1008,1762 ; v1(354,3927) v2(392,3927) 983,3927 1008,3927 ; 1016,1762 1008,1762 ; 1016,3927 1008,3927 ; v1(1052,1718) 1008,1762 ; v1(1052,3883) 1008,3927 ; P2.1@2706,1631 2706,1697 2641,1762 ; P2.1@2706,3796 2706,3862 2641,3927 ; P10.32@3449,1982 3293,2138 3022,2138 2940,2056 2940,1849 2853,1762 2641,1762 ; P10.32@3449,4147 3293,4303 3022,4303 2940,4221 2940,4014 2853,3927 2641,3927 ; v1(4170.93,1762) v2(4208.93,1762) 4799.93,1762 4824.93,1762 ; v1(4170.93,3927) v2(4208.93,3927) 4799.93,3927 4824.93,3927 ; 4832.93,1762 4824.93,1762 ; 4832.93,3927 4824.93,3927 ; v1(4868.93,1718) 4824.93,1762 ; v1(4868.93,3883) 4824.93,3927 ; P2.1@6522.93,1631 6522.93,1697 6457.93,1762 ; P2.1@6522.93,3796 6522.93,3862 6457.93,3927 ; P10.32@7265.93,1982 7109.93,2138 6838.93,2138 6756.93,2056 6756.93,1849 6669.93,1762 6457.93,1762 ; P10.32@7265.93,4147 7109.93,4303 6838.93,4303 6756.93,4221 6756.93,4014 6669.93,3927 6457.93,3927 ; 1008,1762 2616,1762 2641,1762 ; 1008,3927 2616,3927 2641,3927 ; 4824.93,1762 6432.93,1762 6457.93,1762 ; 4824.93,3927 6432.93,3927 6457.93,3927
BOOT0: P6.3 R18.2 U3.94 | length 5823.3
  Top Layer w10: v1(1551,1420) 1581.89,1389.11 U3.94@1581.89,1287.13 ; v1(1551,3585) 1581.89,3554.11 U3.94@1581.89,3452.13 ; v1(2422,1579) 2432.47,1568.53 2432.47,1499.53 R18.2@2502,1430 v1(2543,1430) ; v1(2422,3744) 2432.47,3733.53 2432.47,3664.53 R18.2@2502,3595 v1(2543,3595) ; v1(5367.93,1420) 5398.82,1389.11 U3.94@5398.82,1287.13 ; v1(5367.93,3585) 5398.82,3554.11 U3.94@5398.82,3452.13 ; v1(6238.93,1579) 6249.4,1568.53 6249.4,1499.53 R18.2@6318.93,1430 v1(6359.93,1430) ; v1(6238.93,3744) 6249.4,3733.53 6249.4,3664.53 R18.2@6318.93,3595 v1(6359.93,3595)
  Bottom Layer w10: v1(1551,1420) 2109,1420 2268,1579 v1(2422,1579) ; v1(1551,3585) 2109,3585 2268,3744 v1(2422,3744) ; v1(2543,1430) 2543,1368.94 P6.3@2606,1305.94 ; v1(2543,3595) 2543,3533.94 P6.3@2606,3470.94 ; v1(5367.93,1420) 5925.93,1420 6084.93,1579 v1(6238.93,1579) ; v1(5367.93,3585) 5925.93,3585 6084.93,3744 v1(6238.93,3744) ; v1(6359.93,1430) 6359.93,1368.94 P6.3@6422.93,1305.94 ; v1(6359.93,3595) 6359.93,3533.94 P6.3@6422.93,3470.94
CH340_DN: R2.2 U1.7 | length 3666.8
  Top Layer w10: R2.2@438,1627 465,1627 480,1612 480,1453 566,1367 932,1367 961,1396 961,1455 934.39,1481.61 U1.7@850.17,1481.61 ; R2.2@438,3792 465,3792 480,3777 480,3618 566,3532 932,3532 961,3561 961,3620 934.39,3646.61 U1.7@850.17,3646.61 ; R2.2@4254.93,1627 4281.93,1627 4296.93,1612 4296.93,1453 4382.93,1367 4748.93,1367 4777.93,1396 4777.93,1455 4751.31,1481.61 U1.7@4667.1,1481.61 ; R2.2@4254.93,3792 4281.93,3792 4296.93,3777 4296.93,3618 4382.93,3532 4748.93,3532 4777.93,3561 4777.93,3620 4751.31,3646.61 U1.7@4667.1,3646.61
CH340_DP: R4.2 U1.6 | length 3741.6
  Top Layer w10: R4.2@438,1557 438,1459 547,1350 948,1350 981,1383 981,1474 947.8,1507.2 U1.6@850.17,1507.2 ; R4.2@438,3722 438,3624 547,3515 948,3515 981,3548 981,3639 947.8,3672.2 U1.6@850.17,3672.2 ; R4.2@4254.93,1557 4254.93,1459 4363.93,1350 4764.93,1350 4797.93,1383 4797.93,1474 4764.72,1507.2 U1.6@4667.1,1507.2 ; R4.2@4254.93,3722 4254.93,3624 4363.93,3515 4764.93,3515 4797.93,3548 4797.93,3639 4764.72,3672.2 U1.6@4667.1,3672.2
GND: C1.1 C2.1 C3.1 C4.1 C5.1 C6.2 C7.1 C8.1 C9.1 C10.1 C11.1 C12.1 C13.1 C14.2 C15.2 C16.1 C17.2 C18.2 C19.2 C20.2 C21.2 D1.2 J1.4 J1.5 J1.6 J1.7 J1.8 J1.9 J2.4 J2.5 J2.6 J2.7 J2.8 J2.9 J3.4 J3.6 J3.8 J3.10 J3.12 J3.14 J3.16 J3.18 J3.20 L2.1 P5.3 P10.1 P10.2 P10.3 R5.1 R6.2 R18.1 S2.2 U1.8 U2.1 U3.10 U3.27 U3.49 U3.74 U3.99
  other v2: 1561,379 5377.93,379 3025,398 6841.93,398 2974,399 6790.93,399 2923,401 6739.93,401 639,433 4455.93,433 1452,480 5268.93,480 2479,495 2578,495 6295.93,495 6394.93,495 664,556 4480.93,556 1008,558 4824.93,558 942,560 4758.93,560 600,565 4416.93,565 1336,579 5152.93,579 1167,663 4983.93,663 2129,709 5945.93,709 984,748 4800.93,748 2573,762 6389.93,762 604,778 4420.93,778 2572,799 6388.93,799 1585,833 1655.33,833 1725.67,833 1796,833 5401.93,833 5472.26,833 5542.6,833 5612.93,833 705,904 4521.93,904 771,944 4587.93,944 1585,952 1655.33,952 1725.67,952 1796,952 5401.93,952 5472.26,952 5542.6,952 5612.93,952 688,1005 4504.93,1005 959,1024 4775.93,1024 1585,1071 1655.33,1071 1725.67,1071 1796,1071 5401.93,1071 5472.26,1071 5542.6,1071 5612.93,1071 2034,1293 2086,1293 5850.93,1293 5902.93,1293 924,1407 4740.93,1407 1219,1408 1374,1408 5035.93,1408 5190.93,1408 924,1449 4740.93,1449 526,1493 665,1493 4342.93,1493 4481.93,1493 526,1542 597,1542 668,1542 4342.93,1542 4413.93,1542 4484.93,1542 2189,1637 2241,1637 2291,1637 6005.93,1637 6057.93,1637 6107.93,1637 1400,1649 5216.93,1649 1356,1650 5171,1651 1096,1717 4912.93,1717 1561,2544 5377.93,2544 3025,2563 6841.93,2563 2974,2564 6790.93,2564 2923,2566 6739.93,2566 639,2598 4455.93,2598 1452,2645 5268.93,2645 2479,2660 2578,2660 6295.93,2660 6394.93,2660 664,2721 4480.93,2721 1008,2723 4824.93,2723 942,2725 4758.93,2725 600,2730 4416.93,2730 1336,2744 5152.93,2744 1167,2828 4983.93,2828 2129,2874 5945.93,2874 984,2913 4800.93,2913 2573,2927 6389.93,2927 604,2943 4420.93,2943 2572,2964 6388.93,2964 1585,2998 1655.33,2998 1725.67,2998 1796,2998 5401.93,2998 5472.26,2998 5542.6,2998 5612.93,2998 705,3069 4521.93,3069 771,3109 4587.93,3109 1585,3117 1655.33,3117 1725.67,3117 1796,3117 5401.93,3117 5472.26,3117 5542.6,3117 5612.93,3117 688,3170 4504.93,3170 959,3189 4775.93,3189 1585,3236 1655.33,3236 1725.67,3236 1796,3236 5401.93,3236 5472.26,3236 5542.6,3236 5612.93,3236 2034,3458 2086,3458 5850.93,3458 5902.93,3458 924,3572 4740.93,3572 1219,3573 1374,3573 5035.93,3573 5190.93,3573 924,3614 4740.93,3614 526,3658 665,3658 4342.93,3658 4481.93,3658 526,3707 597,3707 668,3707 4342.93,3707 4413.93,3707 4484.93,3707 2189,3802 2241,3802 2291,3802 6005.93,3802 6057.93,3802 6107.93,3802 1400,3814 5216.93,3814 1354,3816 5172,3816 1096,3882 4912.93,3882
LD-: D2.2 P10.4 | length 2663.8
  Top Layer w10: D2.2@2860.5,769 v1(2906,769) ; D2.2@2860.5,2934 v1(2906,2934) ; D2.2@6677.42,769 v1(6722.93,769) ; D2.2@6677.42,2934 v1(6722.93,2934)
  Bottom Layer w10: v1(2906,769) 2940,735 3296,735 P10.4@3449,582 ; v1(2906,2934) 2940,2900 3296,2900 P10.4@3449,2747 ; v1(6722.93,769) 6756.93,735 7112.93,735 P10.4@7265.93,582 ; v1(6722.93,2934) 6756.93,2900 7112.93,2900 P10.4@7265.93,2747
NetC3_2: C3.2 U1.9 Y1.2 | length 1703
  Top Layer w10: Y1.2@596,1658 629,1625 C3.2@745,1625 787,1583 787,1451 807.57,1430.43 U1.9@850.17,1430.43 ; Y1.2@596,3823 629,3790 C3.2@745,3790 787,3748 787,3616 807.57,3595.43 U1.9@850.17,3595.43 ; Y1.2@4412.93,1658 4445.93,1625 C3.2@4561.93,1625 4603.93,1583 4603.93,1451 4624.5,1430.43 U1.9@4667.1,1430.43 ; Y1.2@4412.93,3823 4445.93,3790 C3.2@4561.93,3790 4603.93,3748 4603.93,3616 4624.5,3595.43 U1.9@4667.1,3595.43
NetC4_2: C4.2 U1.10 Y1.1 | length 1104.8
  Top Layer w10: Y1.1@596,1458 625,1429 C4.2@745,1429 769.16,1404.84 U1.10@850.17,1404.84 ; Y1.1@596,3623 625,3594 C4.2@745,3594 769.16,3569.84 U1.10@850.17,3569.84 ; Y1.1@4412.93,1458 4441.93,1429 C4.2@4561.93,1429 4586.09,1404.84 U1.10@4667.1,1404.84 ; Y1.1@4412.93,3623 4441.93,3594 C4.2@4561.93,3594 4586.09,3569.84 U1.10@4667.1,3569.84
NetC5_2: C5.2 P3.1 P3.2 R5.2 | length 2184.9
  Top Layer w10: P3.1@2406,415 P3.2@2506,415 ; P3.1@2406,2580 P3.2@2506,2580 ; P3.1@6222.93,415 P3.2@6322.93,415 ; P3.1@6222.93,2580 P3.2@6322.93,2580
  Top Layer w12: R5.2@2358,584 v1(2413,584) ; R5.2@2358,2749 v1(2413,2749) ; v1(2413,769) C5.2@2457.23,769 ; v1(2413,2934) C5.2@2457.23,2934 ; R5.2@6174.93,584 v1(6229.93,584) ; R5.2@6174.93,2749 v1(6229.93,2749) ; v1(6229.93,769) C5.2@6274.16,769 ; v1(6229.93,2934) C5.2@6274.16,2934
  Bottom Layer w12: P3.1@2413,422 v1(2413,769) ; P3.1@2413,2587 v1(2413,2934) ; P3.1@6229.93,422 v1(6229.93,769) ; P3.1@6229.93,2587 v1(6229.93,2934)
NetC7_2: C7.2 R7.1 Y2.2 | length 2081.7
  Top Layer w10: Y2.2@641,912 663,912 C7.2@746,995 755,995 975.14,1215.14 R7.1@1009,1215.14 982.14,1215.14 ; Y2.2@641,3077 663,3077 C7.2@746,3160 755,3160 975.14,3380.14 R7.1@1009,3380.14 982.14,3380.14 ; Y2.2@4457.93,912 4479.93,912 C7.2@4562.93,995 4571.93,995 4792.07,1215.14 R7.1@4825.93,1215.14 4799.07,1215.14 ; Y2.2@4457.93,3077 4479.93,3077 C7.2@4562.93,3160 4571.93,3160 4792.07,3380.14 R7.1@4825.93,3380.14 4799.07,3380.14
NetC11_2: C11.2 R9.1 Y2.1 | length 2520.6
  Top Layer w10: Y2.1@567.65,891.35 Y2.1@567.65,912 ; Y2.1@567.65,904.35 607,865 C11.2@746,865 757,865 797,905 797,971 964.29,1138.29 R9.1@1009,1138.29 ; Y2.1@567.65,3056.35 Y2.1@567.65,3077 ; Y2.1@567.65,3069.35 607,3030 C11.2@746,3030 757,3030 797,3070 797,3136 964.29,3303.29 R9.1@1009,3303.29 ; Y2.1@4384.58,891.35 Y2.1@4384.58,912 ; Y2.1@4384.58,904.35 4423.93,865 C11.2@4562.93,865 4573.93,865 4613.93,905 4613.93,971 4781.21,1138.29 R9.1@4825.93,1138.29 ; Y2.1@4384.58,3056.35 Y2.1@4384.58,3077 ; Y2.1@4384.58,3069.35 4423.93,3030 C11.2@4562.93,3030 4573.93,3030 4613.93,3070 4613.93,3136 4781.21,3303.29 R9.1@4825.93,3303.29
NetC12_2: C12.2 R13.1 R14.1 Y3.2 | length 2448.8
  Top Layer w12: Y3.2@601,700 C12.2@746,700 762,700 790,728 790,867 R14.1@897,974 986.57,974 R13.1@1009,996.43 ; Y3.2@601,2865 C12.2@746,2865 762,2865 790,2893 790,3032 R14.1@897,3139 986.57,3139 R13.1@1009,3161.43 ; Y3.2@4417.93,700 C12.2@4562.93,700 4578.93,700 4606.93,728 4606.93,867 R14.1@4713.93,974 4803.5,974 R13.1@4825.93,996.43 ; Y3.2@4417.93,2865 C12.2@4562.93,2865 4578.93,2865 4606.93,2893 4606.93,3032 R14.1@4713.93,3139 4803.5,3139 R13.1@4825.93,3161.43
NetC13_2: C13.2 R20.1 Y3.1 | length 864.6
  Top Layer w12: Y3.1@601,500 C13.2@746,500 746,570.67 R20.1@746.33,571 ; Y3.1@601,2665 C13.2@746,2665 746,2735.67 R20.1@746.33,2736 ; Y3.1@4417.93,500 C13.2@4562.93,500 4562.93,570.67 R20.1@4563.26,571 ; Y3.1@4417.93,2665 C13.2@4562.93,2665 4562.93,2735.67 R20.1@4563.26,2736
NetC14_1: C14.1 C15.1 R19.1 U3.22 | length 2872.9
  Top Layer w12: v1(1301,557) 1301,776 1330.83,805.83 U3.22@1395.87,805.83 ; v1(1301,2722) 1301,2941 1330.83,2970.83 U3.22@1395.87,2970.83 ; v1(5117.93,557) 5117.93,776 5147.76,805.83 U3.22@5212.79,805.83 ; v1(5117.93,2722) 5117.93,2941 5147.76,2970.83 U3.22@5212.79,2970.83
  Top Layer w24: C14.1@1067,519 R19.1@1067,677 ; C14.1@1067,2684 R19.1@1067,2842 ; C14.1@4883.93,519 R19.1@4883.93,677 ; C14.1@4883.93,2684 R19.1@4883.93,2842
  Bottom Layer w24: v2(1067,557) v1(1301,557) ; v2(1067,2722) v1(1301,2722) ; v2(4883.93,557) v1(5117.93,557) ; v2(4883.93,2722) v1(5117.93,2722)
NetD1_1: D1.1 R8.1 | length 346
  Top Layer w16: R8.1@748,1216 D1.1@834.5,1216 ; R8.1@748,3381 D1.1@834.5,3381 ; R8.1@4564.93,1216 D1.1@4651.43,1216 ; R8.1@4564.93,3381 D1.1@4651.43,3381
NetD2_1: D2.1 R12.1 | length 307.2
  Top Layer w10: R12.1@2720.7,769 D2.1@2797.5,769 ; R12.1@2720.7,2934 D2.1@2797.5,2934 ; R12.1@6537.63,769 D2.1@6614.43,769 ; R12.1@6537.63,2934 D2.1@6614.43,2934
NetJ2_2: J2.2 R2.1 | length 732.6
  Top Layer w10: J2.2@212,1585.59 290.59,1585.59 332,1627 R2.1@378,1627 ; J2.2@212,3750.59 290.59,3750.59 332,3792 R2.1@378,3792 ; J2.2@4028.93,1585.59 4107.52,1585.59 4148.93,1627 R2.1@4194.93,1627 ; J2.2@4028.93,3750.59 4107.52,3750.59 4148.93,3792 R2.1@4194.93,3792
NetJ2_3: J2.3 R4.1 | length 669
  Top Layer w10: J2.3@212,1560 375,1560 R4.1@378,1557 ; J2.3@212,3725 375,3725 R4.1@378,3722 ; J2.3@4028.93,1560 4191.93,1560 R4.1@4194.93,1557 ; J2.3@4028.93,3725 4191.93,3725 R4.1@4194.93,3722
NetP1_1: P1.1 U1.3 | length 4663.7
  Top Layer w10: U1.3@850.17,1583.98 896.98,1583.98 v1(922,1609) ; U1.3@850.17,3748.98 896.98,3748.98 v1(922,3774) ; U1.3@4667.1,1583.98 4713.91,1583.98 v1(4738.93,1609) ; U1.3@4667.1,3748.98 4713.91,3748.98 v1(4738.93,3774)
  Bottom Layer w10: v1(922,1609) 930,1601 1960,1601 P1.1@1990,1631 ; v1(922,3774) 930,3766 1960,3766 P1.1@1990,3796 ; v1(4738.93,1609) 4746.93,1601 5776.93,1601 P1.1@5806.93,1631 ; v1(4738.93,3774) 4746.93,3766 5776.93,3766 P1.1@5806.93,3796
NetP1_3: P1.3 U1.4 | length 4649.8
  Top Layer w10: U1.4@850.17,1558.39 937.39,1558.39 v1(951,1572) ; U1.4@850.17,3723.39 937.39,3723.39 v1(951,3737) ; U1.4@4667.1,1558.39 4754.31,1558.39 v1(4767.93,1572) ; U1.4@4667.1,3723.39 4754.31,3723.39 v1(4767.93,3737)
  Bottom Layer w10: v1(951,1572) 1949,1572 P1.3@1990,1531 ; v1(951,3737) 1949,3737 P1.3@1990,3696 ; v1(4767.93,1572) 5765.93,1572 P1.3@5806.93,1531 ; v1(4767.93,3737) 5765.93,3737 P1.3@5806.93,3696
NetP5_2: P5.2 R16.1 | length 3777.3
  Top Layer w10: R16.1@3377,213 v1(3377,379) ; R16.1@3377,2378 v1(3377,2544) ; R16.1@7193.93,213 v1(7193.93,379) ; R16.1@7193.93,2378 v1(7193.93,2544)
  Bottom Layer w10: P5.2@2655,515 2973,515 3061,427 3329,427 v1(3377,379) ; P5.2@2655,2680 2973,2680 3061,2592 3329,2592 v1(3377,2544) ; P5.2@6471.93,515 6789.93,515 6877.93,427 7145.93,427 v1(7193.93,379) ; P5.2@6471.93,2680 6789.93,2680 6877.93,2592 7145.93,2592 v1(7193.93,2544)
NetR6_1: R6.1 U3.19 | length 961.1
  Top Layer w12: R6.1@1214,766.71 1214,797 1281.89,864.89 U3.19@1395.87,864.89 ; R6.1@1214,2931.71 1214,2962 1281.89,3029.89 U3.19@1395.87,3029.89 ; R6.1@5030.93,766.71 5030.93,797 5098.82,864.89 U3.19@5212.79,864.89 ; R6.1@5030.93,2931.71 5030.93,2962 5098.82,3029.89 U3.19@5212.79,3029.89
NetR13_2: R13.2 U3.12 | length 1245.8
  Top Layer w10: R13.2@1069,996.43 1075.26,1002.68 U3.12@1377.87,1002.68 ; R13.2@1069,3161.43 1075.26,3167.68 U3.12@1377.87,3167.68 ; R13.2@4885.93,996.43 4892.18,1002.68 U3.12@5194.79,1002.68 ; R13.2@4885.93,3161.43 4892.18,3167.68 U3.12@5194.79,3167.68
NetR14_2: R14.2 R15.1 R20.2 | length 1830.9
  Top Layer w12: R20.2@746.33,633 816,702.67 816,833 R14.2@897,914 902.57,919.57 R15.1@1009,919.57 ; R20.2@746.33,2798 816,2867.67 816,2998 R14.2@897,3079 902.57,3084.57 R15.1@1009,3084.57 ; R20.2@4563.26,633 4632.93,702.67 4632.93,833 R14.2@4713.93,914 4719.5,919.57 R15.1@4825.93,919.57 ; R20.2@4563.26,2798 4632.93,2867.67 4632.93,2998 R14.2@4713.93,3079 4719.5,3084.57 R15.1@4825.93,3084.57
NetR15_2: R15.2 U3.13 | length 1412.5
  Top Layer w10: R15.2@1069,919.57 1132.43,983 U3.13@1395.86,983 ; R15.2@1069,3084.57 1132.43,3148 U3.13@1395.86,3148 ; R15.2@4885.93,919.57 4949.36,983 U3.13@5212.79,983 ; R15.2@4885.93,3084.57 4949.36,3148 U3.13@5212.79,3148
NetR16_2: R16.2 S1.2 | length 841.6
  Top Layer w10: R16.2@3437,213 3437,145 3483.83,98.17 S1.2@3560,98.17 ; R16.2@3437,2378 3437,2310 3483.83,2263.17 S1.2@3560,2263.17 ; R16.2@7253.93,213 7253.93,145 7300.76,98.17 S1.2@7376.93,98.17 ; R16.2@7253.93,2378 7253.93,2310 7300.76,2263.17 S1.2@7376.93,2263.17
NRST: C17.1 J3.15 R17.1 S2.1 U3.14 | length 16937.9
  Top Layer w10: v1(903,719) 903,519 v1(980,442) ; v1(903,2884) 903,2684 v1(980,2607) ; v1(1095,773) 1074.14,773 C17.1@1067,765.86 R17.1@1067,842.71 1072.71,842.71 1104,874 1104,925 1142.32,963.32 U3.14@1395.87,963.32 ; v1(1095,2938) 1074.14,2938 C17.1@1067,2930.86 R17.1@1067,3007.71 1072.71,3007.71 1104,3039 1104,3090 1142.32,3128.32 U3.14@1395.87,3128.32 ; v1(3186,363) S2.1@3234.83,314.17 ; v1(3186,2528) S2.1@3234.83,2479.17 ; S2.1@3229.17,314.17 S2.1@3234.83,314.17 ; S2.1@3229.17,2479.17 S2.1@3234.83,2479.17 ; S2.1@3242,314.17 S2.1@3234.83,314.17 ; S2.1@3242,2479.17 S2.1@3234.83,2479.17 ; v1(4719.93,719) 4719.93,519 v1(4796.93,442) ; v1(4719.93,2884) 4719.93,2684 v1(4796.93,2607) ; v1(4911.93,773) 4891.07,773 C17.1@4883.93,765.86 R17.1@4883.93,842.71 4889.64,842.71 4920.93,874 4920.93,925 4959.24,963.32 U3.14@5212.79,963.32 ; v1(4911.93,2938) 4891.07,2938 C17.1@4883.93,2930.86 R17.1@4883.93,3007.71 4889.64,3007.71 4920.93,3039 4920.93,3090 4959.24,3128.32 U3.14@5212.79,3128.32 ; v1(7002.93,363) S2.1@7051.76,314.17 ; v1(7002.93,2528) S2.1@7051.76,2479.17 ; S2.1@7046.09,314.17 S2.1@7051.76,314.17 ; S2.1@7046.09,2479.17 S2.1@7051.76,2479.17 ; S2.1@7058.93,314.17 S2.1@7051.76,314.17 ; S2.1@7058.93,2479.17 S2.1@7051.76,2479.17
  Bottom Layer w10: J3.15@149,440 200,389 927,389 v1(980,442) 2258,442 2337,363 v1(3186,363) ; J3.15@149,2605 200,2554 927,2554 v1(980,2607) 2258,2607 2337,2528 v1(3186,2528) ; v1(903,719) 957,773 v1(1095,773) ; v1(903,2884) 957,2938 v1(1095,2938) ; J3.15@3965.93,440 4016.93,389 4743.93,389 v1(4796.93,442) 6074.93,442 6153.93,363 v1(7002.93,363) ; J3.15@3965.93,2605 4016.93,2554 4743.93,2554 v1(4796.93,2607) 6074.93,2607 6153.93,2528 v1(7002.93,2528) ; v1(4719.93,719) 4773.93,773 v1(4911.93,773) ; v1(4719.93,2884) 4773.93,2938 v1(4911.93,2938)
